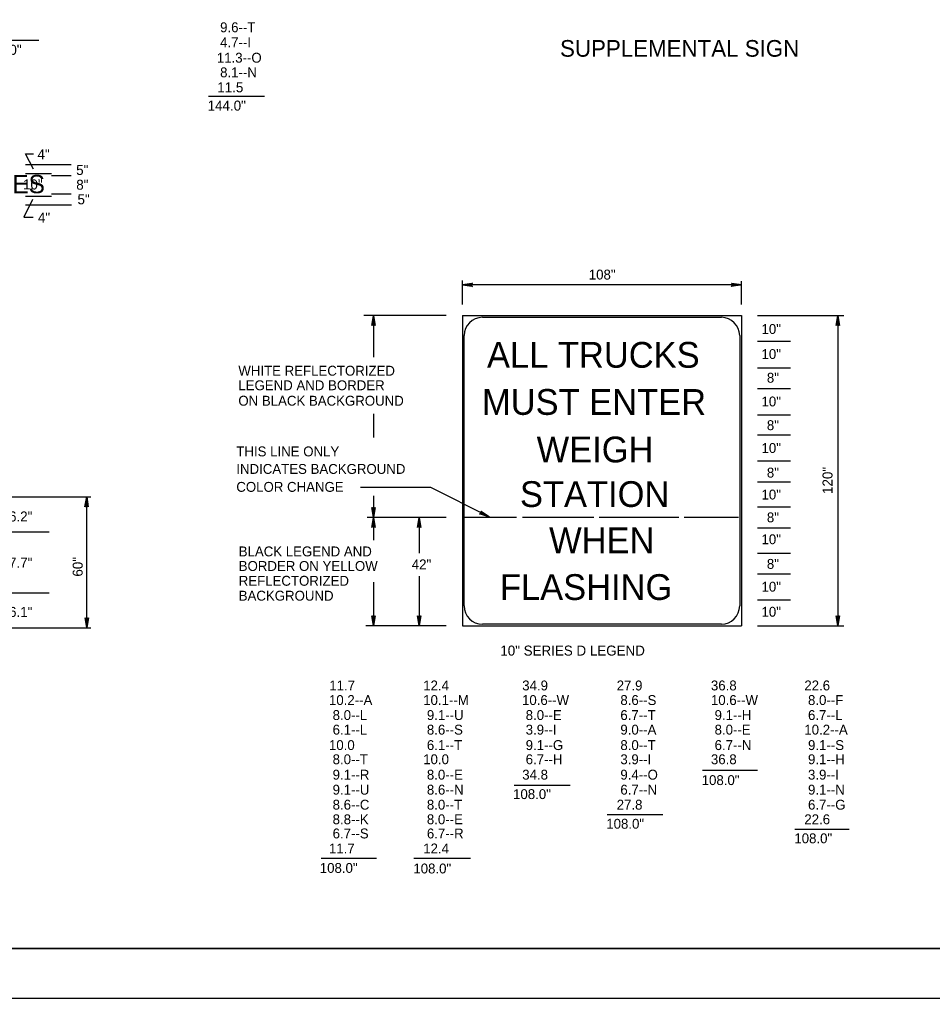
# Model space of a CAD drawing. Extents: x 649604 to 650509, y 298458 to 299646.
# Drawn here: x 649933.2 to 650206.9, y 298457.6 to 298751.1 of the extents above; entities that cross this region are included whole.
import ezdxf

# ---------------------------------------------------------------- set-up
doc = ezdxf.new("R2010")
doc.units = 0
for name, color, linetype in [('1', 7, 'Continuous'), ('2', 7, 'Continuous'), ('3', 7, 'Continuous'), ('PLT-BNDY', 7, 'Continuous')]:
    doc.layers.add(name, color=color, linetype=linetype)

# ---------------------------------------------------------------- blocks, each defined once
blk = doc.blocks.new('RARROW')
at = {"layer": '3'}
blk.add_lwpolyline([(-2.2695, 0.285), (-2.184875, 0.12075), (0, 0), (-2.2695, 0.285), (-2.38575, 0.384625), (0, 0), (-2.183125, -0.108), (-2.262875, -0.2705), (0, 0), (-2.38575, -0.379125), (-2.262875, -0.2705)], dxfattribs=at)

msp = doc.modelspace()

# ---------------------------------------------------------------- linework, layer by layer
at = {"layer": '1'}
for p, q in [((650430.31, 298472.63), (649644.31, 298472.63)), ((649644.31, 298472.63), (650230.31, 298472.63))]:
    msp.add_line(p, q, dxfattribs=at)
at = {"layer": '2'}
for p, q in [((649922.15, 298744.93), (649938.95, 298744.93)), ((649989.85, 298728.2), (650006.65, 298728.2)), ((649937.38, 298706.29), (649934.99, 298710.86)), ((649934.99, 298710.86), (649937.38, 298710.86)), ((649934.95, 298707.68), (649948.69, 298707.68)), ((649934.95, 298705.01), (649942.83, 298705.01)), ((649942.83, 298704.35), (649948.69, 298704.35)), ((649942.83, 298698.85), (649948.69, 298698.85)), ((649937.1, 298697.16), (649934.5, 298691.89)), ((649934.95, 298698.18), (649942.83, 298698.18)), ((649934.95, 298695.6), (649948.81, 298695.6)), ((649934.5, 298691.89), (649937.31, 298691.89)), ((650065.96, 298665.68), (650065.96, 298672.85)), ((650149.58, 298665.68), (650149.58, 298672.73)), ((650149.58, 298671.6), (650065.96, 298671.6)), ((650061.11, 298662.35), (650036.46, 298662.35)), ((650039.33, 298662.35), (650039.33, 298649.85)), ((650065.96, 298662.35), (650149.58, 298662.35)), ((650065.96, 298662.35), (650065.96, 298569.35)), ((650071.96, 298661.85), (650143.58, 298661.85)), ((650149.58, 298662.35), (650149.58, 298569.35)), ((650154.46, 298662.35), (650180.33, 298662.35)), ((650178.46, 298662.35), (650178.46, 298569.35)), ((650066.46, 298575.35), (650066.46, 298656.35)), ((650149.08, 298656.35), (650149.08, 298575.35)), ((650154.46, 298654.73), (650164.35, 298654.73)), ((650154.46, 298646.73), (650164.35, 298646.73)), ((650154.46, 298640.48), (650164.35, 298640.48)), ((650039.33, 298632.89), (650039.33, 298625.86)), ((650154.46, 298632.6), (650164.35, 298632.6)), ((650154.46, 298626.6), (650164.35, 298626.6)), ((650154.46, 298618.85), (650164.35, 298618.85)), ((650056.46, 298610.85), (650035.43, 298610.85)), ((650073.96, 298601.98), (650056.46, 298610.85)), ((650154.46, 298612.48), (650164.35, 298612.48)), ((649927.06, 298608.01), (649954.58, 298608.01)), ((649953.33, 298568.76), (649953.33, 298608.01)), ((650039.33, 298608.37), (650039.33, 298601.85)), ((650154.46, 298604.98), (650164.35, 298604.98)), ((650061.11, 298601.85), (650037.44, 298601.85)), ((650039.33, 298601.85), (650039.33, 298594.98)), ((650052.96, 298601.85), (650052.96, 298591.15)), ((650082.21, 298601.85), (650066.71, 298601.85)), ((650105.33, 298601.85), (650083.96, 298601.85)), ((650130.83, 298601.85), (650106.96, 298601.85)), ((650148.71, 298601.85), (650132.46, 298601.85)), ((649927.06, 298597.51), (649942.12, 298597.51)), ((650154.46, 298598.73), (650164.35, 298598.73)), ((650154.46, 298591.1), (650164.35, 298591.1)), ((650052.96, 298584.21), (650052.96, 298569.35)), ((650154.46, 298584.98), (650164.35, 298584.98)), ((650039.33, 298582.48), (650039.33, 298569.35)), ((649927.06, 298579.26), (649942.12, 298579.26)), ((650154.46, 298577.1), (650164.35, 298577.1)), ((650143.58, 298569.85), (650071.96, 298569.85)), ((649927.06, 298568.76), (649954.58, 298568.76)), ((650061.11, 298569.35), (650036.99, 298569.35)), ((650065.96, 298569.35), (650149.58, 298569.35)), ((650154.46, 298569.35), (650180.33, 298569.35)), ((650137.98, 298526.1), (650154.45, 298526.1)), ((650081.43, 298521.6), (650098.23, 298521.6)), ((650109.38, 298512.73), (650126.02, 298512.73)), ((650165.6, 298508.35), (650181.92, 298508.35)), ((650023.6, 298499.73), (650040.24, 298499.73)), ((650051.38, 298499.73), (650068.35, 298499.73))]:
    msp.add_line(p, q, dxfattribs=at)
for centre, start, end in [((650071.96, 298656.35), 90, 180), ((650143.58, 298656.35), 0, 90), ((650071.96, 298575.35), 180, 270), ((650143.58, 298575.35), 270, 0)]:
    msp.add_arc(centre, 5.5, start, end, dxfattribs=at)
at = {"layer": 'PLT-BNDY'}
msp.add_lwpolyline([(649604.31, 299051.63), (650445.31, 299051.63), (650445.31, 298457.63), (649604.31, 298457.63)], close=True, dxfattribs=at)

# ---------------------------------------------------------------- block references
at = {"layer": '2', "xscale": 1.2574347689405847}
for p, yscale, rotation in [((650065.96, 298671.6), 1.3092961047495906, 180), ((650039.33, 298662.35), 1.3092961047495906, 89.99999999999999), ((650178.46, 298662.35), 1.3092961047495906, 89.99999999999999), ((649953.33, 298608.01), 1.3092961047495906, 89.99999999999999), ((650039.33, 298601.85), 1.3092961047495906, -90.00000000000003), ((650039.33, 298601.85), 1.3092961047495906, 89.99999999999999), ((650052.96, 298601.85), 1.3092961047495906, 89.99999999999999), ((650073.96, 298601.98), 1.3092961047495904, -26.538667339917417), ((649953.33, 298568.76), 1.3092961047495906, -90.00000000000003), ((650039.33, 298569.35), 1.3092961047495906, -90.00000000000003), ((650052.96, 298569.35), 1.3092961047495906, -90.00000000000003), ((650178.46, 298569.35), 1.3092961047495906, -90.00000000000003)]:
    msp.add_blockref('RARROW', p, dxfattribs=dict(at, yscale=yscale, rotation=rotation))
at = {"layer": '2', "xscale": 1.2574347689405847, "yscale": 1.3092961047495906}
msp.add_blockref('RARROW', (650149.58, 298671.6), dxfattribs=at)

# ---------------------------------------------------------------- texts
at = {"layer": '2'}
for s, height, p in [(' 9.6--T', 2.966, (649992.23, 298747.32)), (' 4.7--I', 2.966, (649992.23, 298742.82)), ('144.0"', 3, (649922.36, 298740.55)), ('SUPPLEMENTAL SIGN', 5, (650095.23, 298739.98)), ('11.3--O', 2.966, (649992.35, 298738.2)), (' 8.1--N', 2.966, (649992.23, 298733.82)), ('11.5', 3, (649992.48, 298729.32)), ('144.0"', 3, (649989.59, 298723.82)), ('4"', 3, (649938.59, 298709.23)), ('5"', 3, (649950.18, 298704.52)), ('NEXT REST AREA    MILES', 5.5, (649847.23, 298699.05)), ('10"', 3, (649934.25, 298700.18)), ('8"', 3, (649950.21, 298700.11)), ('5"', 3, (649950.58, 298695.73)), ('4"', 3, (649938.73, 298690.26)), ('108"', 2.966, (650103.85, 298673.18)), ('10"', 2.966, (650155.62, 298656.86)), ('ALL TRUCKS', 7.728, (650073.33, 298646.73)), ('10"', 2.966, (650155.62, 298649.35)), ('WHITE REFLECTORIZED', 2.9663, (649998.8, 298644.35)), ('LEGEND AND BORDER', 2.9663, (649998.8, 298639.98)), ('8"', 2.966, (650157.23, 298642.24)), ('MUST ENTER', 7.728, (650071.83, 298632.6)), ('ON BLACK BACKGROUND', 2.9663, (649998.8, 298635.35)), ('10"', 2.966, (650155.62, 298635.13)), ('8"', 2.966, (650157.23, 298628.02)), ('WEIGH', 7.728, (650088.21, 298618.35)), ('THIS LINE ONLY', 2.9663, (649998.19, 298620.15)), ('10"', 2.966, (650155.62, 298621.18)), ('INDICATES BACKGROUND', 2.9663, (649998.19, 298614.9)), ('8"', 2.966, (650157.23, 298613.8)), ('COLOR CHANGE', 2.9663, (649998.19, 298609.52)), ('STATION', 7.728, (650083.21, 298604.98)), ('10"', 2.966, (650155.62, 298607.22)), ('16.2"', 3, (649927.82, 298600.63)), ('8"', 2.966, (650157.23, 298600.38)), ('WHEN', 7.728, (650091.96, 298591.1)), ('10"', 2.966, (650155.62, 298593.81)), ('BLACK LEGEND AND', 2.9663, (649998.91, 298590.17)), ('27.7"', 3, (649927.82, 298586.76)), ('BORDER ON YELLOW', 2.9663, (649998.91, 298585.8)), ('42"', 2.966, (650050.79, 298586.29)), ('8"', 2.966, (650157.23, 298586.43)), ('REFLECTORIZED', 2.9663, (649998.91, 298581.36)), ('FLASHING', 7.728, (650077.21, 298577.1)), ('10"', 2.966, (650155.62, 298579.59)), ('BACKGROUND', 2.966, (649998.91, 298576.89)), ('16.1"', 3, (649927.82, 298572.01)), ('10"', 2.966, (650155.62, 298572.08)), (' 10" SERIES D LEGEND', 3, (650076.21, 298560.42)), ('11.7    ', 2.966, (650026.06, 298549.98)), ('12.4   ', 2.966, (650054.21, 298549.98)), ('34.9', 2.966, (650083.9, 298549.98)), ('27.9   ', 2.966, (650112.21, 298549.98)), ('36.8   ', 2.966, (650140.46, 298549.98)), ('22.6   ', 2.966, (650168.46, 298549.98)), ('10.2--A', 2.966, (650025.96, 298545.6)), ('10.1--M', 2.966, (650054.21, 298545.6)), ('10.6--W', 2.966, (650083.83, 298545.6)), (' 8.6--S', 2.966, (650112.21, 298545.6)), ('10.6--W', 2.966, (650140.46, 298545.6)), (' 8.0--F', 2.966, (650168.46, 298545.6)), (' 8.0--L', 2.966, (650025.96, 298541.1)), (' 9.1--U', 2.966, (650054.21, 298541.1)), (' 8.0--E', 2.966, (650083.83, 298541.1)), (' 6.7--T', 2.966, (650112.21, 298541.1)), (' 9.1--H', 2.966, (650140.46, 298541.1)), (' 6.7--L', 2.966, (650168.46, 298541.1)), (' 6.1--L', 2.966, (650025.96, 298536.73)), (' 8.6--S', 2.966, (650054.21, 298536.73)), (' 3.9--I', 2.966, (650083.83, 298536.73)), (' 9.0--A', 2.966, (650112.21, 298536.73)), (' 8.0--E', 2.966, (650140.46, 298536.73)), ('10.2--A', 2.966, (650168.46, 298536.73)), ('10.0   ', 2.966, (650025.96, 298532.1)), (' 6.1--T', 2.966, (650054.21, 298532.1)), (' 9.1--G', 2.966, (650083.83, 298532.1)), (' 8.0--T', 2.966, (650112.21, 298532.1)), (' 6.7--N', 2.966, (650140.46, 298532.1)), (' 9.1--S', 2.966, (650168.46, 298532.1)), (' 8.0--T', 2.966, (650025.96, 298527.85)), ('10.0   ', 2.966, (650054.21, 298527.85)), (' 6.7--H', 2.966, (650083.83, 298527.85)), (' 3.9--I', 2.966, (650112.21, 298527.85)), ('36.8   ', 2.966, (650140.46, 298527.85)), (' 9.1--H', 2.966, (650168.46, 298527.85)), (' 9.1--R', 2.966, (650025.96, 298523.23)), (' 8.0--E', 2.966, (650054.21, 298523.23)), ('34.8   ', 2.966, (650083.9, 298523.23)), (' 9.4--O', 2.966, (650112.21, 298523.23)), (' 3.9--I', 2.966, (650168.46, 298523.23)), ('108.0"', 2.966, (650137.69, 298521.6)), (' 9.1--U', 2.966, (650025.96, 298518.73)), (' 8.6--N', 2.966, (650054.21, 298518.73)), ('108.0"', 2.966, (650081.15, 298517.4)), (' 6.7--N', 2.966, (650112.21, 298518.73)), (' 9.1--N', 2.966, (650168.46, 298518.73)), (' 8.6--C', 2.966, (650025.96, 298514.23)), (' 8.0--T', 2.966, (650054.21, 298514.23)), ('27.8   ', 2.966, (650112.21, 298514.23)), (' 6.7--G', 2.966, (650168.46, 298514.23)), (' 8.8--K', 2.966, (650025.96, 298509.85)), (' 8.0--E', 2.966, (650054.21, 298509.85)), ('108.0"', 2.966, (650109.09, 298508.51)), ('22.6   ', 2.966, (650168.46, 298509.85)), (' 6.7--S', 2.966, (650025.96, 298505.6)), (' 6.7--R', 2.966, (650054.21, 298505.6)), ('108.0"', 2.966, (650165.47, 298504.15)), ('11.7   ', 2.966, (650025.96, 298501.1)), ('12.4   ', 2.966, (650054.21, 298501.1)), ('108.0" ', 2.966, (650023.21, 298495.26)), ('108.0"', 2.966, (650051.26, 298495.1))]:
    msp.add_text(s, height=height, dxfattribs=at).set_placement(p)
for s, p in [('120"', (650176.91, 298608.88)), ('60"', (649952.14, 298584.1))]:
    msp.add_text(s, height=3, rotation=90, dxfattribs=at).set_placement(p)

doc.saveas('drawing.dxf')
